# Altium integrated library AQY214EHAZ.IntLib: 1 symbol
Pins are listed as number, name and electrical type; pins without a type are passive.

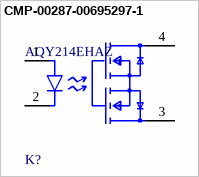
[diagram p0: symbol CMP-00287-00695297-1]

## CMP-00287-00695297-1
designator K?, comment AQY214EHAZ
AQY214EHAZ Relay Ssr 50MA 1.5V Dc-in 0.12A 400V Ac/dc-out 4-PIN DIP SMD T/r; NexarPartId: 695297; Max Power Dissipation: 550mW; Max Output Current: 120mA; Input Current: 30mA; Max Junction Temperature (Tj): 125°C; Resistance: 35Ω; Throw Configuration: SPST; On-State Resistance: 26Ω; Capacitance: 800fF; Isolation Voltage: 5kV; Output Voltage: 320V; Number of Contacts: 1
footprint FP-AQY214EHAZ-IPC_C
footprint FP-AQY214EHAZ-MFG
footprint FP-AQY214EHAZ-IPC_A
footprint FP-AQY214EHAZ-IPC_B
pins: 1 A, 2 C, 3 1 DRAIN, 4 2 DRAIN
